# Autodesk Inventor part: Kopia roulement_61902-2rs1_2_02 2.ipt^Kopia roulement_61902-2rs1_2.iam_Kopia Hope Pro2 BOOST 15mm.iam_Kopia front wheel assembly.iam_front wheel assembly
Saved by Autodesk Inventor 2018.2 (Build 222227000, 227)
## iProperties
Created: 2017-09
Part Number: Kopia roulement_61902-2rs1_2_02 2.ipt^Kopia roulement_61902-2rs1_2.iam_Kopia Hope Pro2 BOOST 15mm.iam_Kopia front wheel assembly.iam_front wheel assembly
Material: Ogólny
Document SubType Name: Modeling
Designer: Tomasz
Density: 1 g/cm^3
Appearance: Domyślna
Author: Tomasz
Sending System: SolidWorks 2017
Last Author: Tomasz
Last Saved: 2017-09-11
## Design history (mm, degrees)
